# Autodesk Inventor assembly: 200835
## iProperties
Created: 2007-12
Part Number: 200835
Document SubType Name: Assembly
Designer: MM
Mass: 4124.04 g
Surface Area: 6054.57 cm^2
Volume: 524.766 cm^3
Density: 7.85882 g/cm^3
Description: TOP FRAME ASSEMBLY
Component Category: Lower Component
Author: MM
